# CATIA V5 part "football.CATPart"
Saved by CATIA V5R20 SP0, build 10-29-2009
Part number: 足球
Material "Bathroom Floor": density 2770 kg/m3, Young's modulus 6e+10 Pa, Poisson ratio 0.3
Material "Black": density 7860 kg/m3, Young's modulus 2e+11 Pa, Poisson ratio 0.266
Material "Black": density 7860 kg/m3, Young's modulus 2e+11 Pa, Poisson ratio 0.266
Material "Black": density 7860 kg/m3, Young's modulus 2e+11 Pa, Poisson ratio 0.266
Material "Black": density 7860 kg/m3, Young's modulus 2e+11 Pa, Poisson ratio 0.266
Material "Black": density 7860 kg/m3, Young's modulus 2e+11 Pa, Poisson ratio 0.266
Material "Black": density 7860 kg/m3, Young's modulus 2e+11 Pa, Poisson ratio 0.266
Material "Black": density 7860 kg/m3, Young's modulus 2e+11 Pa, Poisson ratio 0.266
Material "Black": density 7860 kg/m3, Young's modulus 2e+11 Pa, Poisson ratio 0.266
Material "Black": density 7860 kg/m3, Young's modulus 2e+11 Pa, Poisson ratio 0.266
Material "Black": density 7860 kg/m3, Young's modulus 2e+11 Pa, Poisson ratio 0.266
Material "Black": density 7860 kg/m3, Young's modulus 2e+11 Pa, Poisson ratio 0.266
Material "Black": density 7860 kg/m3, Young's modulus 2e+11 Pa, Poisson ratio 0.266
Bounding box of the stored display mesh (mm): x -102.883 to 102.883, y -102.974 to 102.974, z -239.803 to -33.803
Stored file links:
  D:\CATIAR20\part\football.CATPart
  D:\CATIAR20\win_b64\startup\materials\Catalog.CATMaterial
  D:\CATIAR20\win_b64\startup\materials\blue_env_512x512.jpg
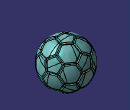
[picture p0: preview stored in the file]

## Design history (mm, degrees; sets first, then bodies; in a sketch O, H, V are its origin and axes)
Body1 (main body), material "Bathroom Floor"
  Sketch1 on xy-plane, origin (0, 0, 0), H (1, 0, 0), V (0, 1, 0)
    circle A1 centre (0, 0) radius 50
  Sketch2 on xy-plane, origin (0, 0, 0), H (1, 0, 0), V (0, 1, 0)
    point P3 (0, 0)
    line L1 (0, 50) -> (47.5528, 15.4508)
    line L2 (47.5528, 15.4508) -> (29.3893, -40.4508)
    line L3 (29.3893, -40.4508) -> (-29.3893, -40.4508)
    line L4 (-29.3893, -40.4508) -> (-47.5528, 15.4508)
    line L5 (-47.5528, 15.4508) -> (0, 50)
    coincidence: P3 H
    horizontal: L3 H
  Line1: type Normal, RefPoint vertex [element of Sketch2 | element of Sketch2], RefSkin xy-plane, Start 0, End 20
  Line2: type PtPt, FirstPoint vertex [element of Sketch2 | element of Sketch2], SecondPoint vertex [element of Sketch2 | element of Sketch2]
  Line3: type PtPt, FirstPoint vertex [element of Sketch2 | element of Sketch2], SecondPoint vertex [element of Sketch2 | element of Sketch2]
  Rotate1: Axis Line1, Angle 120, ToTransfor Line2
  Rotate2: Axis Line1, Angle 240, ToTransfor Line3
  Revol1: Element1 Rotate1, Line Line2, Angle1 0
  Revol2: Element1 Rotate2, Line Line3, Angle1 180
  Intersect1: ToIntersect1 Revol1, ToIntersect2 Revol2
  Point1: type Between, FirstPoint vertex [element of Sketch2 | element of Sketch2], SecondPoint vertex [element of Sketch2 | element of Sketch2], Ratio 0.5
  Plane1: type Normal, Curve Sketch2, RefPoint Point1
  Symmetry1: Reference Plane1, ToTransfor Intersect1
  Line4: type PtPt, FirstPoint vertex of Intersect1, SecondPoint vertex of Symmetry1
  MultiSel1
  Line5: type PtPt, FirstPoint vertex [element of Sketch2 | element of Sketch2], SecondPoint vertex of MultiSel1
  Line6: type PtPt, FirstPoint vertex [element of Sketch2 | element of Sketch2], SecondPoint vertex of MultiSel1
  Intersect2: ToIntersect1 Line6, ToIntersect2 Line5
  Plane2: type 2Lines, Element1 Line4, Element2 Line5
  Line7: type PtDir, RefPoint Intersect2, Direction Plane2, Start 0, End 150
  Line8: type Normal, RefPoint Sketch1.O, RefSkin xy-plane, Start 0, End 150
  Intersect3: ToIntersect1 Line7, ToIntersect2 Line8
  Line9: type PtPt, FirstPoint Point1, SecondPoint Intersect3
  Extrude1: Element1 Line9, Lim1 20, Lim2 0, Direction Line3, FirstUpto vertex [element of Sketch2 | element of Sketch2], SecondUpto vertex [element of Sketch2 | element of Sketch2]
  Rotate3: Axis Line7, Angle 60, ToTransfor Extrude1
  Set1
    Rotate4: Axis Line7, Angle 120 {= Rotate3.Angle+`Rotate4.相对Angle`}, ToTransfor Extrude1
    Rotate5: Axis Line7, Angle 180 {= Rotate4.Angle+`Rotate5.相对Angle`}, ToTransfor Extrude1
    Rotate6: Axis Line7, Angle 240 {= Rotate5.Angle+`Rotate6.相对Angle`}, ToTransfor Extrude1
    Rotate7: Axis Line7, Angle 300 {= Rotate6.Angle+`Rotate7.相对Angle`}, ToTransfor Extrude1
  Rotate8: Axis Line8, Angle 72, ToTransfor Extrude1
  Set2
    Rotate9: Axis Line8, Angle 144 {= Rotate8.Angle+`Rotate9.相对Angle`}, ToTransfor Extrude1
    Rotate10: Axis Line8, Angle 216 {= Rotate9.Angle+`Rotate10.相对Angle`}, ToTransfor Extrude1
    Rotate11: Axis Line8, Angle 288 {= Rotate10.Angle+`Rotate11.相对Angle`}, ToTransfor Extrude1
  Split1 "分割.1": ToCut Extrude1, Cutting (Rotate8; Rotate11)
  Split2 "分割.2": ToCut Rotate8, Cutting (Split1; Rotate9)
  Split3 "分割.3": ToCut Rotate9, Cutting (Rotate10; Split2)
  Split4 "分割.4": ToCut Rotate10, Cutting (Split3; Rotate11)
  Split5 "分割.5": ToCut Rotate11, Cutting (Split4; Split1)
  Split6 "分割.6": ToCut Rotate7, Cutting (Split1; Rotate6)
  Split7 "分割.7": ToCut Rotate6, Cutting (Rotate5; Split6)
  Split8 "分割.8": ToCut Rotate5, Cutting (Split7; Rotate4)
  Split9 "分割.9": ToCut Rotate4, Cutting (Split8; Rotate3)
  Split10 "分割.10": ToCut Rotate3, Cutting (Split9; Split1)
  Join1: Elements Sketch2
  Join2: Elements ({symmetry Reference Line4, ToTransfor Intersect1}; Intersect1; Line3; Symmetry1; {symmetry Reference Line4, ToTransfor Symmetry1}; {symmetry Reference Line4, ToTransfor Line3})
  Sphere1: Center Intersect3, Radius 100, Angle1 -45, Angle3 0, Angle4 180
  Project1: ToProject Join1, Support Sphere1
  Project2: ToProject Join2, Support Sphere1
  Split11: ToCut Sphere1, Cutting Project1
  Sphere2: Center Intersect3, Radius 100, Angle1 -45, Angle3 0, Angle4 180
  Split12: ToCut Sphere2, Cutting Project2
  Set3
    ThickSurface1: Surface Split12, TopOffset 3, BotOffset 0
    ThickSurface2: Surface Split11, TopOffset 3, BotOffset 0
    Fillet1: radius 5, on face of ThickSurface2
    Fillet2: radius 5, on face of ThickSurface1
    Rotate12: Axis Line8, Angle 72, ToTransfor Fillet2
    Rotate13: Axis Line8, Angle 72, ToTransfor Rotate12
    Rotate14: Axis Line8, Angle 72, ToTransfor Rotate13
    Rotate15: Axis Line8, Angle 72, ToTransfor Rotate14
    Point2: type OnCurve, Support edge [face of Rotate15 | face of Rotate15], Ratio 0.5
    Point3: type OnCurve, Support edge [face of Fillet2 | face of ThickSurface1], Ratio 0.5
    Plane3: type 3Points, Element1 Point3, Element2 Point2, Element3 Intersect3
    Symmetry2: Reference Plane3, ToTransfor Fillet1
    Symmetry3: Reference Plane3, ToTransfor Rotate13
    MultiSel2
    MultiSel3
    MultiSel4
    MultiSel5
    MultiSel6
    Point4: (0, 0, 0), relative to vertex [face of Symmetry3 | face of Symmetry3 | face of Symmetry3]
    Point5: (0, 0, 0), relative to vertex [face of Symmetry2 | face of Symmetry2 | face of Symmetry2]
    Plane4: type 3Points, Element1 Point5, Element2 Point4, Element3 Intersect3
    Symmetry4: Reference Plane4, ToTransfor Symmetry3
    Symmetry5: Reference Intersect3, ToTransfor {rotate Axis Line8, Angle 72, ToTransfor {rotate Axis Line8, Angle 72, ToTransfor {rotate Axis Line8, Angle 72, ToTransfor Symmetry2}}}
    MultiSel7
    MultiSel8
    MultiSel9
    MultiSel10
